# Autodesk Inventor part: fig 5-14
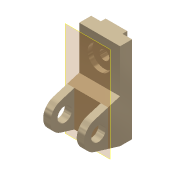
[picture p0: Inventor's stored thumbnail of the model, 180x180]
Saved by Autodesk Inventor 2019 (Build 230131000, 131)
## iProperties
Shininess: 65.0
Angle Display Precision: 2
Document Length Units: 11269
Document Angle Units: 11279
Document Time Units: 11290
Document Mass Units: 11283
Document Length Units Precision: 3
Document Angle Units Precision: 2
Compacted: False
Created: 2001-11
Part Number: fig 5-14
Document SubType Name: Modeling
Designer: Renu Muthoo
Density: 1 g/cm^3
Material: Generic
Appearance: Metal-Titanium (Polished)
Density: 0.0
Volumn: 0.0
Area: 0.0
PropertySet Name: Model Information
Control State: 0
Master: False
Checked Out: False
Author: Renu Muthoo
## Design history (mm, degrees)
node "Sketch1"
sketch "Sketch2"
  geometry: L1 (33.257, 104.664)-(33.257, -75.336); L2 (33.257, -75.336)-(8.257, -75.336); L3 (8.257, -75.336)-(-45.451, -59.045); L4 (-45.451, -1.628)-(8.257, 14.664); L5 (8.257, 14.664)-(8.257, 104.664); L6 (8.257, 104.664)-(33.257, 104.664); C1 r 15 at (-36.743, -30.336); A1 r 30 centre (-36.743, -30.336) between (-45.451, -1.628) and (-45.451, -59.045)
  constraints: 12 end point, 2 centre point, 2 equal length, 2 parallel, 2 point on circle, 2 tangent, 1 coincident, 1 perpendicular, 1 vertical
  dimensions: "d0" = 180 distance of L1.start L1.end; "d1" = 30 radius of A1; "d2" = 25 distance of L5.end L1.start; "d3" = 45 distance from line of L2 A1.centre; "d4" = 70 distance from line of L1 A1.centre; "d5" = 30 diameter of C1
extrude "Extrusion1" new body sketch "Sketch2" distance "d6" = 85; taper "d7" = 0 deg
workplane "Work Plane1"
sketch "Sketch3"
  geometry: L1 (15, 62.364)-(70, 62.364); L2 (70, 62.364)-(70, -52.386); L3 (70, -52.386)-(15, -52.386); L4 (15, -52.386)-(15, 62.364); L5 (0, -45)-(0, -28.708) reference
  constraints: 8 end point, 2 parallel, 1 horizontal, 1 perpendicular
  dimensions: "d8" = 55 distance of L1.start L1.end; "d9" = 15 distance between parallel lines of L5 L4
extrude "Extrusion2" cut sketch "Sketch3" distance "d10" = 50; taper "d11" = 0 deg
sketch "Sketch4"
  geometry: L1 (0, 25)-(85, 25) reference; L2 (0, 0)-(0, 25) reference; L3 (20, 25)-(65, 25); L4 (65, 25)-(65, 35); L5 (65, 35)-(20, 35); L6 (20, 35)-(20, 25)
  constraints: 8 end point, 2 parallel, 1 horizontal, 1 perpendicular, 1 point on line
  dimensions: "d12" = 45 distance of L4.end L5.end; "d13" = 10 distance of L3.end L4.end; "d14" = 20 distance between parallel lines of L2 L6
extrude "Extrusion3" join sketch "Sketch4" stored distance "d15" = 50; taper "d16" = 0 deg
sketch "Sketch5"
  geometry: L1 (85, 0)-(85, 90) reference; L2 (0, 90)-(85, 90) reference; 1 further point
  dimensions: "d17" = 42 distance from line of L2 point (42.5, 48); "d18" = 42.5 distance from line of L1 point (42.5, 48)
hole "Hole1" sketch "Sketch5" at (42.5, 48) diameter "d19" = 20; stored, may be unused: countersink angle "d23" = 82 deg, drill point angle "d25" = 118 deg; dims "d20" = 6, "d21" = 50, "d22" = 10, "d24" = 8
workplane "Work Plane6"
body "Solid1"
other parameters: "d26" = 0
